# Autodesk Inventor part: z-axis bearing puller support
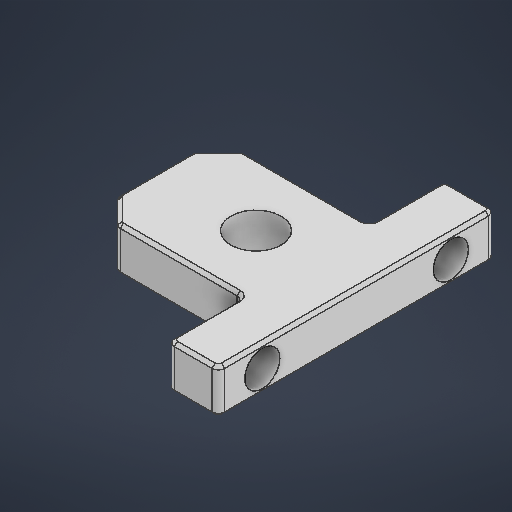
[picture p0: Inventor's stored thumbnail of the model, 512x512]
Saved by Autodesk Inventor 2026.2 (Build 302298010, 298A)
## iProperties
Created: 2026-04
Part Number: z-axis bearing puller support
Material: 일반
Document SubType Name: Modeling
Designer: work
Density: 1 g/cm^3
Appearance: 기본값
Author: work
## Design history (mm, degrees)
sketch "스케치1"
  geometry: L1 (0, 0)-(-8, 0); L2 (8, 5)-(-8, 5); L3 (-8, 5)-(-8, -5); L4 (-8, -5)-(8, -5); L5 (8, -5)-(8, 5); L6 (8, 5)-(-8, -5); L7 (-8, 5)-(8, -5); L8 (-8, 5)-(-4, 5); L9 (-4, 5)-(-4, 11); L10 (-4, 11)-(-8, 11); L11 (-8, 11)-(-8, 5); L12 (-8, -5)-(-4, -5); L13 (-4, -5)-(-4, -11); L14 (-4, -11)-(-8, -11); L15 (-8, -11)-(-8, -5); C1 r 2 at (0, 0); 3 further points
  constraints: 30 end point, 6 parallel, 4 horizontal, 3 perpendicular, 2 midpoint, 1 centre point, 1 coincident
  dimensions: "d0" = 4 diameter of C1; "d1" = 8 distance of L1.start L1.end; "d2" = 16 distance of L4.end L3.end; "d3" = 10 distance of L3.end L2.end; "d4" = 4 distance of L10.end L9.end; "d5" = 6 distance of L9.end L8.end; "d6" = 4 distance of L13.end L14.end; "d7" = 6 distance of L12.end L13.end
extrude "돌출1" new body sketch "스케치1" distance "d8" = 3.5; taper "d9" = 0 deg
sketch "스케치2"
  geometry: L1 (-5, 0)-(-5, 3.5); L2 (6, 3.5)-(-16, 3.5) reference; L3 (-12.5, 1.75)-(2.5, 1.75); C1 r 1.4 at (-12.5, 1.75); C2 r 1.4 at (2.5, 1.75); 1 further point
  constraints: 4 end point, 3 midpoint, 2 centre point, 2 coincident, 1 horizontal
  dimensions: "d10" = 15 distance of L3.start L3.end; "d11" = 2.8 diameter of C1; "d12" = 2.8 diameter of C2
extrude "돌출2" cut sketch "스케치2" extent not by distance; stored distance "d13" = 0; taper "d14" = 0 deg
chamfer "모따기1" distance "d15" = 2; stored, may be unused: second distance "d16" = 2, angle "d17" = 45 deg
fillet "모깎기1" dims "d18" = 0.5
chamfer "모따기2" distance "d19" = 0.25; stored, may be unused: second distance "d20" = 2, angle "d21" = 45 deg
node "솔리드1"
